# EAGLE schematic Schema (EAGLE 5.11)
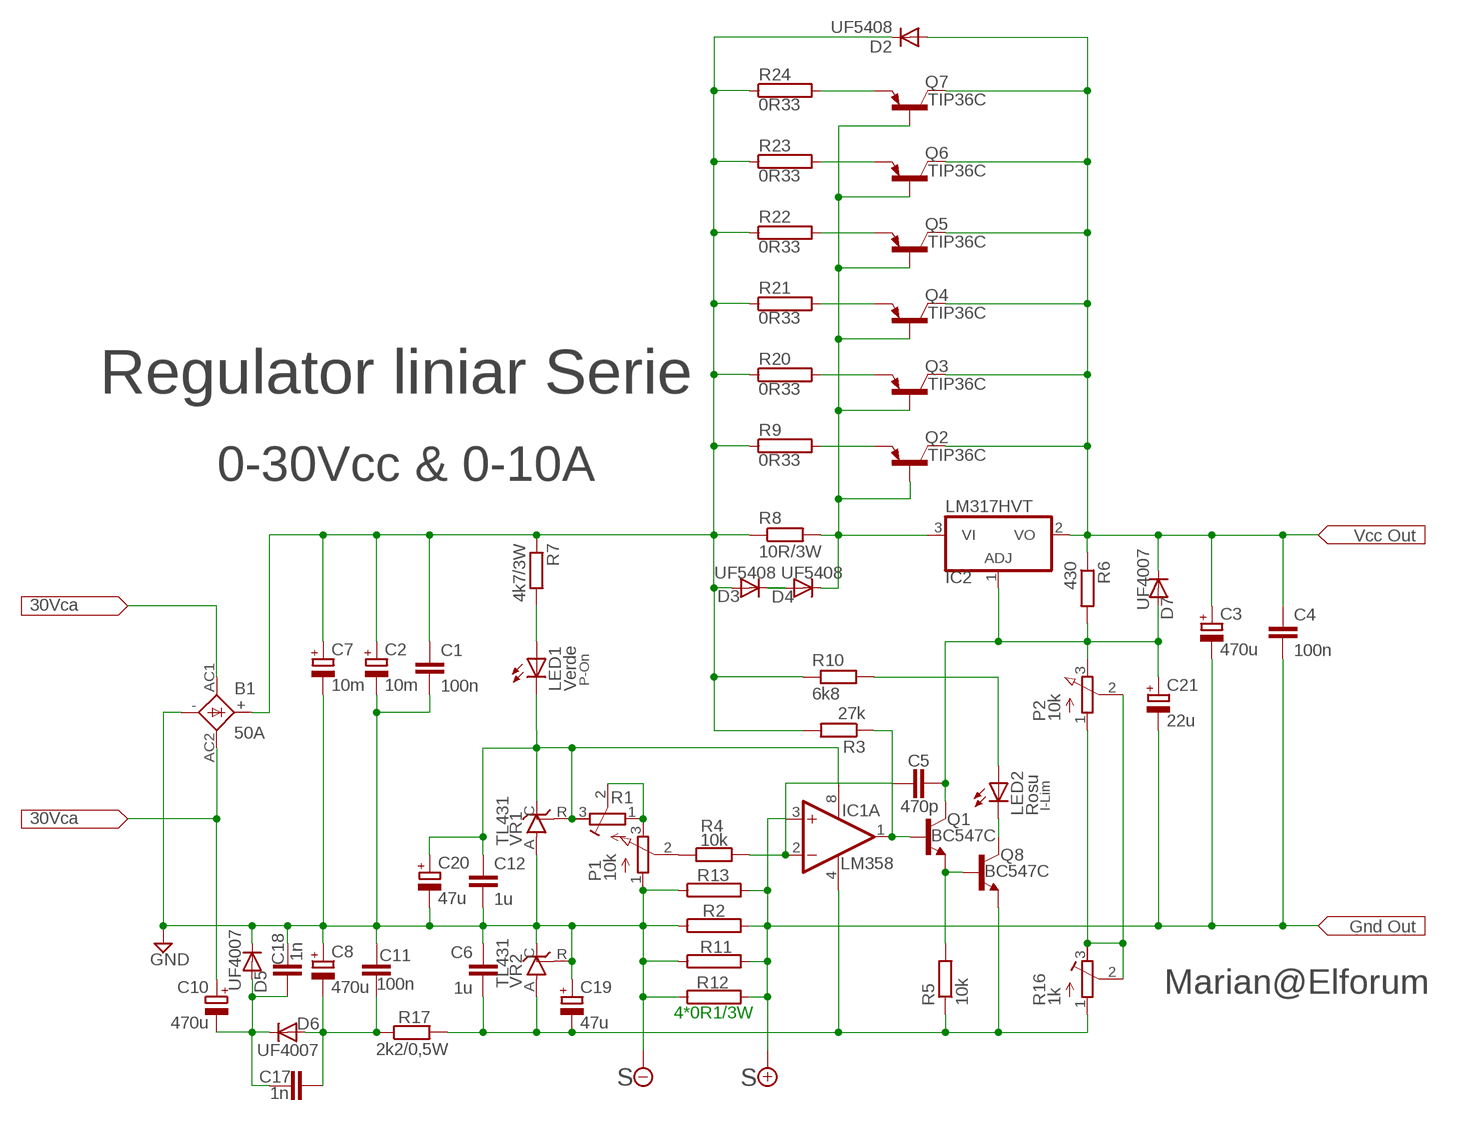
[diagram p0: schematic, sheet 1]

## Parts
B1  50A  2KBB  [2KBB]
C1  100n  C-EU025-050X050  [C025-050X050]
C2  10m  CPOL-EU085CS-1R  [085CS_1R]
C3  470u  CPOL-EU085CS-1R  [085CS_1R]
C4  100n  C-EU025-050X050  [C025-050X050]
C5  470p  C-EU025-050X050  [C025-050X050]
C6  1u  C-EU025-050X050  [C025-050X050]
C7  10m  CPOL-EU085CS-1R  [085CS_1R]
C8  470u  CPOL-EU085CS-1R  [085CS_1R]
C10  470u  CPOL-EU085CS-1R  [085CS_1R]
C11  100n  C-EU025-050X050  [C025-050X050]
C12  1u  C-EU025-050X050  [C025-050X050]
C17  1n  C-EU025-050X050  [C025-050X050]
C18  1n  C-EU025-050X050  [C025-050X050]
C19  47u  CPOL-EU085CS-1R  [085CS_1R]
C20  47u  CPOL-EU085CS-1R  [085CS_1R]
C21  22u  CPOL-EU085CS-1R  [085CS_1R]
D2  UF5408  1N5059  [DO204-10]
D3  UF5408  1N5059  [DO204-10]
D4  UF5408  1N5059  [DO204-10]
D5  UF4007  1N5059  [DO204-10]
D6  UF4007  1N5059  [DO204-10]
D7  UF4007  1N5059  [DO204-10]
IC1  LM358  AD8682R  [SO08]
IC2  LM317HVT  317T  [TO220H]
LED1  Verde  LED3MM  [LED3MM]
LED2  Rosu  LED3MM  [LED3MM]
P1  10k  3RP/1610N  [3RP/1610N]
P2  10k  3RP/1610N  [3RP/1610N]
Q1  BC547C  BC546A  [TO92-EBC]
Q2  TIP36C  BD244  [TO220]
Q3  TIP36C  BD244  [TO220]
Q4  TIP36C  BD244  [TO220]
Q5  TIP36C  BD244  [TO220]
Q6  TIP36C  BD244  [TO220]
Q7  TIP36C  BD244  [TO220]
Q8  BC547C  BC546A  [TO92-EBC]
R1  R-TRIMM70Y  [RTRIM70Y]
R2  100m/5W  RCA4060  [CA4060]
R3  27k  R-EU_0207/7  [0207/7]
R4  10k  R-EU_0207/7  [0207/7]
R5  10k  R-EU_0207/7  [0207/7]
R6  430  R-EU_0207/7  [0207/7]
R7  4k7/3W  R-EU_0207/7  [0207/7]
R8  10R/3W  R-EU_0207/7  [0207/7]
R9  0R33  RCA4050  [CA4050]
R10  6k8  R-EU_0207/7  [0207/7]
R11  100m/5W  RCA4060  [CA4060]
R12  100m/5W  RCA4060  [CA4060]
R13  100m/5W  RCA4060  [CA4060]
R16  1k  R-TRIMM4G/J  [RTRIM4G/J]
R17  2k2/0,5W  R-EU_0207/7  [0207/7]
R20  0R33  RCA4050  [CA4050]
R21  0R33  RCA4050  [CA4050]
R22  0R33  RCA4050  [CA4050]
R23  0R33  RCA4050  [CA4050]
R24  0R33  RCA4050  [CA4050]
VR1  TL431  TL431CLP  [TO92-CLP]
VR2  TL431  TL431CLP  [TO92-CLP]

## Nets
+8V: C3.- C4.2 C21.- IC1.3(A:+IN) R2.2 R11.2 R12.2 R13.2 ; supply symbol labelled S
-5V: B1.- C1.2 C2.- C6.1 C7.- C8.+ C11.1 C12.2 C18.1 C19.+ C20.- D5.C P1.1(A) R2.1 R11.1 R12.1 R13.1 VR1.A VR2.C VR2.R ; supply symbol labelled GND, S
N$1: C6.2 C19.- Q8.E R5.1 R16.1(E) R17.2 VR2.A
N$2: C10.- C17.2 C18.2 D5.A D6.C
N$3: P1.2(S) R4.1
N$4: C12.1 C20.+ IC1.8(P:V+) R1.3(A) VR1.C VR1.R
N$6: P1.3(E) R1.1(E) R1.2(S)
N$7: Q1.E Q8.B R5.2
N$8: B1.+ C1.1 C2.+ C7.+ D2.C D3.A R3.2 R7.1 R8.1 R9.1 R10.1 R20.1 R21.1 R22.1 R23.1 R24.1
N$9: C3.+ C4.1 D2.A D7.C IC2.2(VO) Q2.2(C) Q3.2(C) Q4.2(C) Q5.2(C) Q6.2(C) Q7.2(C) R6.1
N$10: C5.2 C21.+ D7.A IC2.1(ADJ) P2.3(E) Q1.C R6.2
N$11: Q2.3(E) R9.2
N$12: LED1.A R7.2
N$13: LED2.A R10.2
N$14: D4.C IC2.3(VI) Q2.1(B) Q3.1(B) Q4.1(B) Q5.1(B) Q6.1(B) Q7.1(B) R8.2
N$17: LED2.K(C) Q8.C
N$18: C8.- C11.2 C17.1 D6.A R17.1
N$20: IC1.1(A:OUT) IC1.2(A:-IN) Q1.B R3.1 R4.2
N$22: Q3.3(E) R20.2
N$23: Q4.3(E) R21.2
N$24: Q5.3(E) R22.2
N$25: Q6.3(E) R23.2
N$26: Q7.3(E) R24.2
N$30: LED1.K(C)
N$31: P2.1(A) P2.2(S) R16.2(S) R16.3(A)
N$32: B1.AC1
N$33: B1.AC2 C10.+
N$34: D3.C D4.A
Unconnected: C5.1 IC1.5(B:+IN) IC1.6(B:-IN) IC1.7(B:OUT)

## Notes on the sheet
- Regulator liniar Serie
- 0-30Vcc & 0-10A
- P-On
- I-Lim
- Marian@Elforum
- 4*0R1/3W

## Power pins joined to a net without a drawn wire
V-: IC1.4(P:V-)

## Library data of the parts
B1 = rectifier:2KBB: RECTIFIER grid 3 x 5 mm
C1 C4-C6 C11 C12 C17 C18 = resistor:C-EU: CAPACITOR, European symbol
C2 C3 C7 C8 C10 C19-C21 = resistor:CPOL-EU: POLARIZED CAPACITOR, European symbol
D2-D7 = diode2:1N5059: DIODE
IC1 = linear:AD8682: Dual Low Power, High Speed JFET Operational Amplifiers Source: http://www.analog.com/UploadedFiles/Data_Sheets/AD8682_8684.pdf
IC2 = linear:*317: Positive VOLTAGE REGULATOR
LED1 LED2 = led:LED: LED
P1 P2 = pot:3RP/1610N: 16mm Potentiometer one level Source: http://www.alphapotentiometers.net/html/16mm_pot_2.html
Q1 Q8 = transistor-npn:BC546*: NPN Transistor
Q2-Q7 = transistor-pnp:BD244: PNP Transisitor
R1 R16 = resistor:R-TRIMM: Trimm resistor
R2 R9 R11-R13 R20-R24 = resistor-power:R: Power Resitor; OC_FARNELL: unknown; OC_NEWARK: unknown
R3-R8 R10 R17 = resistor:R-EU_: RESISTOR, European symbol
VR1 VR2 = v-reg2:TL431CLP: VOLTAGE REGULATOR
